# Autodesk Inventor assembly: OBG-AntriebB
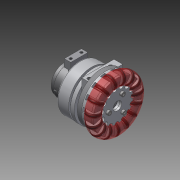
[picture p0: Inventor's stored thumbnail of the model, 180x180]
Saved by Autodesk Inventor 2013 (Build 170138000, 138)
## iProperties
Created: 2012-07
Part Number: OBG-AntriebB
Document SubType Name: Assembly
Designer: rYan
Mass: 195.483 g
Surface Area: 531.242 cm^2
Volume: 71.1581 cm^3
Density: 2.74717 g/cm^3
Author: rYan
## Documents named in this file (8)
- D:\SVN\2013\Inventor\Antrieb\OBG-AntriebB.iam
- D:\SVN\2013\Inventor\Kaufteile\MaxonEC45-30W.ipt
- D:\SVN\2013\Inventor\Kaufteile\Ritzel z15.ipt
- D:\SVN\2013\Inventor\Antrieb\UBG-Rad.iam
- D:\SVN\2013\Inventor\Antrieb\Encoderhalter.ipt
- D:\SVN\2013\Inventor\Kaufteile\E8P-X-157-S-D-M-X\E8P-X-157-S-D-M-X.iam
- D:\SVN\2013\Inventor\Antrieb\LagerbockB.ipt
- D:\SVN\2013\Inventor\Inhaltscenter\de-DE\DIN 7984\DIN 7984 - M3 x 8.ipt
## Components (9 placed, 7 different names)
1. LagerbockB:1 — Passend:3, Winkel:1, Passend:17, Passend:18, Passend:19, Passend:21, Passend:22
2. MaxonEC45-30W:1 — Passend:3, Passend:15, Passend:18, Passend:19, Passend:20, Fluchtend:1, Passend:23
3. Ritzel Z=15:1 — Passend:20, Fluchtend:1
4. UBG-Rad:1 [sub-assembly] — Passend:21, Passend:22
5. Encoderhalter:1 — Passend:12, Passend:13, Passend:14, Passend:15, Winkel:1, Passend:23
6. E8P-X-157-S-D-M-X:1 [sub-assembly] — Passend:12, Passend:13, Passend:14
7. DIN 7984 M3 x 8:1 — Passend:17
8. DIN 7984 M3 x 8:2
9. DIN 7984 M3 x 8:3
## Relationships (14: Mate 12, Angle 1, Flush 1)
- Passend:3 [Mate]: LagerbockB:1 ↔ MaxonEC45-30W:1
- Passend:12 [Mate]: Encoderhalter:1 ↔ E8P-X-157-S-D-M-X:1
- Passend:13 [Mate]: Encoderhalter:1 ↔ E8P-X-157-S-D-M-X:1
- Passend:14 [Mate]: Encoderhalter:1 ↔ E8P-X-157-S-D-M-X:1
- Passend:15 [Mate]: MaxonEC45-30W:1 ↔ Encoderhalter:1
- Winkel:1 [Angle]: LagerbockB:1 ↔ Encoderhalter:1
- Passend:17 [Mate]: LagerbockB:1 ↔ DIN 7984 M3 x 8:1
- Passend:18 [Mate]: LagerbockB:1 ↔ MaxonEC45-30W:1
- Passend:19 [Mate]: LagerbockB:1 ↔ MaxonEC45-30W:1
- Passend:20 [Mate]: MaxonEC45-30W:1 ↔ Ritzel Z=15:1
- Fluchtend:1 [Flush]: MaxonEC45-30W:1 ↔ Ritzel Z=15:1
- Passend:21 [Mate]: LagerbockB:1 ↔ UBG-Rad:1
- Passend:22 [Mate]: LagerbockB:1 ↔ UBG-Rad:1
- Passend:23 [Mate]: MaxonEC45-30W:1 ↔ Encoderhalter:1
